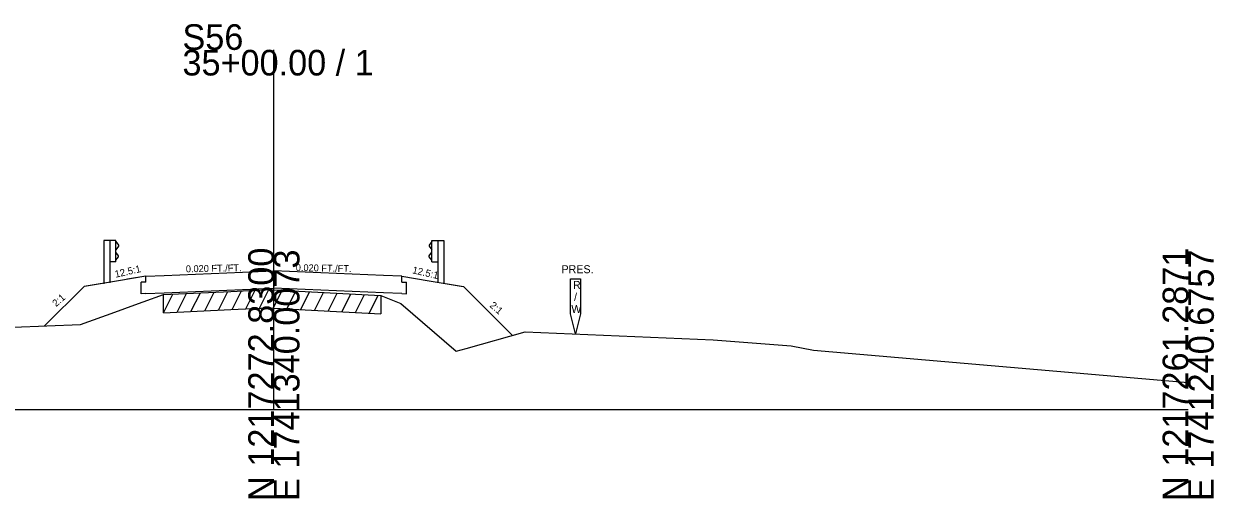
# Model space of a CAD drawing. Extents: x -26 to 1203, y -10 to 19541.
# Drawn here: x 72.6 to 202.8, y 9990.3 to 10042.1 of the extents above; entities that cross this region are included whole.
import ezdxf

# ---------------------------------------------------------------- set-up
doc = ezdxf.new("R2010")
doc.units = 0
for name, color, linetype in [('RD_GPK_XS_Cell', 7, 'Continuous'), ('RD_XS_Base', 7, 'Continuous'), ('RD_XS_EarthShd', 7, 'Continuous'), ('RD_XS_ExGround', 7, 'Continuous'), ('RD_XS_ExPaveRet', 7, 'Continuous'), ('RD_XS_ExRW', 7, 'Continuous'), ('RD_XS_GR', 7, 'Continuous'), ('RD_XS_Pave', 7, 'Continuous'), ('RD_XS_TX_Elev_EX', 7, 'Continuous'), ('RD_XS_TX_Slope', 7, 'Continuous')]:
    doc.layers.add(name, color=color, linetype=linetype)

msp = doc.modelspace()

# ---------------------------------------------------------------- linework, layer by layer
at = {"layer": 'RD_GPK_XS_Cell'}
for p, q in [((100, 10000), (100, 10039.3)), ((0, 10000), (100, 10000)), ((100, 10000), (200, 10000))]:
    msp.add_line(p, q, dxfattribs=at)
at = {"layer": 'RD_XS_Base'}
for p, q in [((86, 10013.93), (86, 10014.57)), ((114, 10013.93), (114, 10014.57)), ((86, 10013.93), (85.5, 10013.91)), ((85.5, 10012.64), (85.5, 10013.91)), ((88, 10012.74), (100, 10013.24)), ((112, 10012.74), (100, 10013.24)), ((114, 10013.93), (114.5, 10013.91)), ((114.5, 10012.64), (114.5, 10013.91)), ((86, 10012.66), (85.5, 10012.64)), ((86, 10012.66), (88, 10012.74)), ((114, 10012.66), (112, 10012.74)), ((114, 10012.66), (114.5, 10012.64))]:
    msp.add_line(p, q, dxfattribs=at)
at = {"layer": 'RD_XS_EarthShd'}
for p, q in [((86, 10014.57), (83, 10014.07)), ((86, 10014.57), (84, 10014.23)), ((114, 10014.57), (117, 10014.07)), ((74.93, 10009.13), (79.25, 10013.44)), ((83, 10014.07), (79.25, 10013.44)), ((83, 10014.07), (79.5, 10013.48)), ((117, 10014.07), (120.5, 10013.48)), ((117, 10014.07), (120.75, 10013.44)), ((120.75, 10013.44), (126.1, 10008.1))]:
    msp.add_line(p, q, dxfattribs=at)
at = {"layer": 'RD_XS_ExGround'}
msp.add_lwpolyline([(71.5, 10009), (78.85, 10009.27), (82.61, 10010.63), (84.79, 10011.42), (85.71, 10011.78), (87.93, 10012.56), (95.28, 10012.91), (99.39, 10013.1), (100, 10013.07), (107.53, 10012.66), (111.7, 10012.46), (113.89, 10011.59), (119.94, 10006.37), (121.04, 10006.67), (127.48, 10008.48), (148.06, 10007.61), (156.58, 10006.94), (159.02, 10006.49), (200, 10002.95)], dxfattribs=at)
at = {"layer": 'RD_XS_ExPaveRet'}
for p, q in [((95.43, 10010.92), (96.45, 10012.97)), ((96.93, 10010.99), (97.95, 10013.04)), ((98.43, 10011.06), (99.45, 10013.1)), ((99.93, 10011.07), (100.91, 10013.02)), ((87.93, 10010.56), (88.96, 10012.61)), ((87.93, 10010.56), (87.93, 10012.56)), ((89.43, 10010.63), (90.46, 10012.68)), ((90.93, 10010.7), (91.96, 10012.75)), ((92.43, 10010.78), (93.46, 10012.83)), ((93.93, 10010.85), (94.96, 10012.9)), ((101.43, 10010.99), (102.41, 10012.94)), ((102.93, 10010.91), (103.91, 10012.86)), ((104.43, 10010.83), (105.41, 10012.78)), ((105.93, 10010.75), (106.91, 10012.7)), ((107.43, 10010.67), (108.41, 10012.62)), ((108.93, 10010.59), (109.91, 10012.55)), ((110.43, 10010.52), (111.41, 10012.47)), ((111.7, 10012.46), (111.7, 10010.46)), ((87.93, 10010.56), (95.28, 10010.91)), ((95.28, 10010.91), (99.39, 10011.1)), ((99.39, 10011.1), (100, 10011.07)), ((100, 10011.07), (107.53, 10010.66)), ((107.53, 10010.66), (111.7, 10010.46))]:
    msp.add_line(p, q, dxfattribs=at)
at = {"layer": 'RD_XS_ExRW'}
msp.add_lwpolyline([(132.45, 10014.27), (133.55, 10014.27), (133.55, 10010.44), (133, 10008.25), (132.45, 10010.44)], close=True, dxfattribs=at)
at = {"layer": 'RD_XS_GR'}
for p, q in [((81.4, 10018.48), (81.4, 10013.72)), ((82.06, 10018.48), (81.4, 10018.48)), ((82.06, 10018.48), (82.06, 10013.83)), ((82.73, 10018.48), (82.06, 10018.48)), ((82.73, 10016.15), (82.73, 10018.48)), ((82.73, 10018.34), (83, 10017.94)), ((117.27, 10018.34), (117, 10017.94)), ((117.27, 10016.15), (117.27, 10018.48)), ((117.27, 10018.48), (117.94, 10018.48)), ((117.94, 10018.48), (117.94, 10013.83)), ((117.94, 10018.48), (118.6, 10018.48)), ((118.6, 10018.48), (118.6, 10013.72)), ((83, 10017.84), (82.73, 10017.44)), ((83, 10016.8), (82.73, 10017.2)), ((83, 10017.94), (83, 10017.84)), ((117, 10017.94), (117, 10017.84)), ((117, 10017.84), (117.27, 10017.44)), ((117, 10016.8), (117.27, 10017.2)), ((82.73, 10016.15), (82.06, 10016.15)), ((82.73, 10016.3), (83, 10016.7)), ((83, 10016.7), (83, 10016.8)), ((117, 10016.7), (117, 10016.8)), ((117.27, 10016.3), (117, 10016.7)), ((117.27, 10016.15), (117.94, 10016.15))]:
    msp.add_line(p, q, dxfattribs=at)
at = {"layer": 'RD_XS_Pave'}
for p, q in [((86, 10014.57), (88, 10014.65)), ((88, 10014.65), (100, 10015.15)), ((112, 10014.65), (100, 10015.15)), ((114, 10014.57), (112, 10014.65))]:
    msp.add_line(p, q, dxfattribs=at)

# ---------------------------------------------------------------- texts
at = {"layer": 'RD_GPK_XS_Cell'}
for s, p in [('S56', (90, 10039.3)), ('35+00.00 / 1', (90, 10036.5))]:
    msp.add_text(s, height=2.8, dxfattribs=at).set_placement(p)
for s, p in [('N 1217272.8300', (100, 9990)), ('E 1741340.0073', (102.8, 9990)), ('N 1217261.2871', (200, 9990)), ('E 1741240.6757', (202.8, 9990))]:
    msp.add_text(s, height=2.8, rotation=90, dxfattribs=at).set_placement(p)
at = {"layer": 'RD_XS_ExRW'}
for s, p in [('PRES.', (131.45, 10014.89)), ('R', (132.71, 10013.17)), ('/', (132.83, 10011.86)), ('W', (132.53, 10010.55))]:
    msp.add_text(s, height=0.875, dxfattribs=at).set_placement(p)
at = {"layer": 'RD_XS_TX_Elev_EX'}
msp.add_text('847.53', height=0.1, rotation=90, dxfattribs=at).set_placement((100.1, 10013.07))
at = {"layer": 'RD_XS_TX_Slope'}
for s, height, rotation, p in [('12.5:1', 0.778, 12.7511, (82.69, 10014.39)), ('0.020 FT./FT.', 0.7518, 1.1916, (90.38, 10014.99)), ('0.020 FT./FT.', 0.7518, 358.8084, (102.39, 10015.14)), ('12.5:1', 0.778, 347.2489, (115.09, 10014.89)), ('2:1', 0.778, 40.6589, (76.17, 10011.18)), ('2:1', 0.778, 319.3411, (123.53, 10011.27))]:
    msp.add_text(s, height=height, rotation=rotation, dxfattribs=at).set_placement(p)

doc.saveas('drawing.dxf')
